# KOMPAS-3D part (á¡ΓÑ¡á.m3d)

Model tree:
1. Эскиз:1
2. Операция выдавливания:1
     Расстояние 1 = 4
3. Эскиз:2
4. Операция выдавливания:2
     Расстояние 1 = 4; Угол 1 = 5
5. Эскиз:3
6. Операция выдавливания:3
     Расстояние 1 = 0.5
7. Эскиз:4
8. Операция выдавливания:4
     Расстояние 1 = 0.5
9. Эскиз:5
10. Операция выдавливания:5
     Расстояние 1 = 0.5
11. Эскиз:6
12. Операция выдавливания:6
     Расстояние 1 = 9
13. Эскиз:7
14. Операция выдавливания:7
     Расстояние 1 = 4; Угол 1 = 7
15. Эскиз:8
16. Операция выдавливания:8
     Расстояние 1 = 15
17. Эскиз:9
18. Операция выдавливания:9
     Расстояние 1 = 0.2
19. Скругление:1
     Радиус = 0.2
20. Массив по концентрической сетке:1  (with: Операция выдавливания:9, Скругление:1)  (labels: Экземпляр ( 1, 1 ); Экземпляр ( 1, 2 ); Экземпляр ( 1, 3 ); Экземпляр ( 1, 4 ))
     N 2 = 6; Шаг 2 = 360; Номер 2 = 1
21. Скругление:2
     Радиус = 0.2
22. Скругление:3
     Радиус = 0.2
23. Скругление:4
     Радиус = 0.2
24. Скругление:5
     Радиус = 0.2
25. Скругление:6
     Радиус = 0.2
26. Эскиз:10
27. Вырезать элемент выдавливания:1
     Расстояние 1 = 37.5
28. Скругление:7
     Радиус = 0.2

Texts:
  Сплав АЛ8  ГОСТ 1583-93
